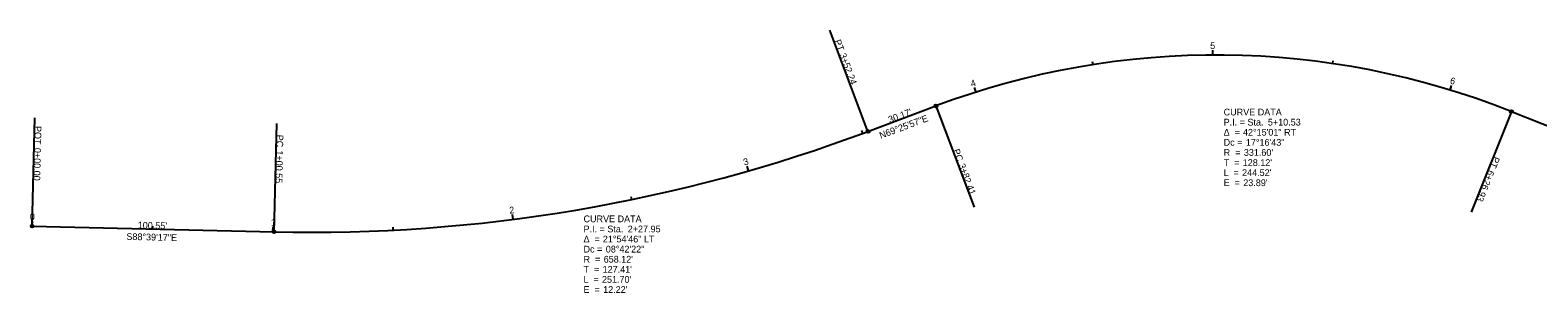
# Model space of a CAD drawing. Extents: x 2001143 to 2002244, y 252727 to 252963.
# Drawn here: x 2001143 to 2001769, y 252823 to 252933 of the extents above; entities that cross this region are included whole.
import ezdxf

# ---------------------------------------------------------------- set-up
doc = ezdxf.new("R2010")
doc.units = 0
for name, color, linetype in [('DT_P_Break_Line', 7, 'Continuous'), ('DT_P_Contour_Major', 7, 'Continuous'), ('DT_P_Contour_Minor', 7, 'Continuous'), ('DT_P_Spot_Elevations', 7, 'Continuous'), ('DT_P_Void', 7, 'Continuous'), ('DT_X_Contour_Minor', 7, 'Continuous'), ('DT_X_Spot_Elev', 7, 'Continuous')]:
    doc.layers.add(name, color=color, linetype=linetype)

msp = doc.modelspace()

# ---------------------------------------------------------------- linework, layer by layer
at = {"layer": 'DT_P_Break_Line'}
for p, q in [((2001490.69, 252890.46), (2001474.88, 252932.6)), ((2001633.98, 252922.2), (2001633.98, 252924.2)), ((2001535.56, 252906.8), (2001535.2, 252907.95)), ((2001732.54, 252907.66), (2001732.89, 252908.81)), ((2001518.94, 252901.06), (2001534.75, 252858.93)), ((2001757.95, 252898.74), (2001741.32, 252856.92)), ((2001143.52, 252851.06), (2001144.57, 252896.05)), ((2001244.04, 252848.7), (2001245.09, 252893.68)), ((2001441.1, 252874.07), (2001440.77, 252875.22)), ((2001343.26, 252853.87), (2001343.11, 252855.06)), ((2001143.52, 252851.06), (2001143.56, 252853.06)), ((2001243.49, 252848.71), (2001243.52, 252849.91))]:
    msp.add_line(p, q, dxfattribs=at)
for centre in [(2001518.94, 252901.06), (2001757.95, 252898.74), (2001490.69, 252890.46), (2001143.52, 252851.06), (2001244.04, 252848.7)]:
    msp.add_circle(centre, 0.6, dxfattribs=at)
at = {"layer": 'DT_P_Contour_Minor'}
for p, q in [((2001490.69, 252890.46), (2001518.94, 252901.06)), ((2001757.95, 252898.74), (2001890.21, 252846.15)), ((2001143.52, 252851.06), (2001244.04, 252848.7))]:
    msp.add_line(p, q, dxfattribs=at)
for centre, radius, start, end in [((2001635.43, 252590.6), 331.6, 68.31729, 110.5675), ((2001635.43, 252590.6), 331.6, 68.31729, 110.5675), ((2001259.49, 253506.63), 658.12, 268.65462, 290.5675), ((2001259.49, 253506.63), 658.12, 268.65462, 290.5675)]:
    msp.add_arc(centre, radius, start, end, dxfattribs=at)
at = {"layer": 'DT_P_Spot_Elevations'}
for p, q in [((2001490.69, 252890.46), (2001474.88, 252932.6)), ((2001633.98, 252922.2), (2001633.98, 252924.2)), ((2001584.19, 252918.22), (2001584.01, 252919.4)), ((2001683.81, 252918.65), (2001683.99, 252919.84)), ((2001535.56, 252906.8), (2001534.96, 252908.71)), ((2001732.54, 252907.66), (2001733.13, 252909.57)), ((2001518.94, 252901.06), (2001534.75, 252858.93)), ((2001757.95, 252898.74), (2001741.32, 252856.92)), ((2001143.52, 252851.06), (2001144.57, 252896.05)), ((2001244.04, 252848.7), (2001245.09, 252893.68)), ((2001488.59, 252889.68), (2001488.17, 252890.8)), ((2001441.1, 252874.07), (2001440.55, 252875.99)), ((2001392.56, 252862.11), (2001392.32, 252863.29)), ((2001343.26, 252853.87), (2001343.01, 252855.85)), ((2001143.52, 252851.06), (2001143.56, 252853.06)), ((2001193.5, 252849.88), (2001193.53, 252851.08)), ((2001243.49, 252848.71), (2001243.54, 252850.71)), ((2001293.47, 252849.39), (2001293.41, 252850.59))]:
    msp.add_line(p, q, dxfattribs=at)
for centre in [(2001518.94, 252901.06), (2001757.95, 252898.74), (2001490.69, 252890.46), (2001143.52, 252851.06), (2001244.04, 252848.7)]:
    msp.add_circle(centre, 0.6, dxfattribs=at)
at = {"layer": 'DT_X_Contour_Minor'}
for p, q in [((2001490.69, 252890.46), (2001474.88, 252932.6)), ((2001633.98, 252922.2), (2001633.98, 252923.4)), ((2001518.94, 252901.06), (2001534.75, 252858.93)), ((2001757.95, 252898.74), (2001741.32, 252856.92)), ((2001143.52, 252851.06), (2001144.57, 252896.05)), ((2001244.04, 252848.7), (2001245.09, 252893.68)), ((2001143.52, 252851.06), (2001143.56, 252853.06))]:
    msp.add_line(p, q, dxfattribs=at)
for centre in [(2001518.94, 252901.06), (2001757.95, 252898.74), (2001490.69, 252890.46), (2001143.52, 252851.06), (2001244.04, 252848.7)]:
    msp.add_circle(centre, 0.6, dxfattribs=at)

# ---------------------------------------------------------------- texts
at = {"layer": 'DT_P_Break_Line'}
for s, rotation, p in [('PT', 290.5675, (2001476.63, 252928.06)), ('5', 0.24994, (2001632.85, 252924.74)), ('3+52.24', 290.5675, (2001478.77, 252922.37)), ('POT', 268.65462, (2001144.54, 252892.75)), ('PC', 268.65462, (2001245.03, 252889.1)), ('0+00.00', 268.65462, (2001144.33, 252883.62)), ('1+00.55', 268.65462, (2001244.88, 252882.58)), ('PC', 290.5675, (2001525.93, 252882.57)), ('PT', 248.31729, (2001750.66, 252880.29)), ('3+82.41', 290.5675, (2001528.22, 252876.47)), ('6+26.93', 248.31729, (2001748.41, 252874.63)), ('0', 358.65462, (2001142.47, 252853.63))]:
    msp.add_text(s, height=2.8, rotation=rotation, dxfattribs=at).set_placement(p)
at = {"layer": 'DT_P_Contour_Major'}
for s, rotation, p in [("30.17'", 20.5675, (2001499.74, 252893.91)), ('N69°25\'57"E', 20.5675, (2001496.03, 252887.34)), ('S88°39\'17"E', 358.65462, (2001182.59, 252845.34)), ("100.55'", 358.65462, (2001187.29, 252850.08))]:
    msp.add_text(s, height=2.8, rotation=rotation, dxfattribs=at).set_placement(p)
for s, p in [('CURVE DATA', (2001638.44, 252897.1)), ('P.I. = Sta. ', (2001638.44, 252892.9)), ('5+10.53', (2001656.81, 252892.9)), ('Δ  = ', (2001638.44, 252888.7)), ('Dc = ', (2001638.44, 252884.5)), ('42°15\'01" RT', (2001646.46, 252888.7)), ('17°16\'43"', (2001647.68, 252884.5)), ('R  = ', (2001638.44, 252880.3)), ("331.60'", (2001646.81, 252880.3)), ('T  = ', (2001638.44, 252876.1)), ('L  = ', (2001638.44, 252871.9)), ("244.52'", (2001646.09, 252871.9)), ("128.12'", (2001646.37, 252876.1)), ('E  = ', (2001638.44, 252867.7)), ("23.89'", (2001646.59, 252867.7)), ('CURVE DATA', (2001372.52, 252852.68)), ('P.I. = Sta. ', (2001372.52, 252848.48)), ('2+27.95', (2001390.89, 252848.48)), ('Δ  = ', (2001372.52, 252844.28)), ('Dc = ', (2001372.52, 252840.08)), ('21°54\'46" LT', (2001380.54, 252844.28)), ('08°42\'22"', (2001381.76, 252840.08)), ('R  = ', (2001372.52, 252835.88)), ("658.12'", (2001380.89, 252835.88)), ('T  = ', (2001372.52, 252831.68)), ('L  = ', (2001372.52, 252827.48)), ("251.70'", (2001380.17, 252827.48)), ("127.41'", (2001380.45, 252831.68)), ('E  = ', (2001372.52, 252823.28)), ("12.22'", (2001380.67, 252823.28))]:
    msp.add_text(s, height=2.8, dxfattribs=at).set_placement(p)
at = {"layer": 'DT_P_Spot_Elevations'}
for s, rotation, p in [('PT', 290.5675, (2001476.63, 252928.06)), ('5', 0.24994, (2001632.85, 252924.74)), ('3+52.24', 290.5675, (2001478.77, 252922.37)), ('4', 17.52864, (2001533.79, 252908.87)), ('6', 342.97124, (2001732.22, 252910.42)), ('POT', 268.65462, (2001144.54, 252892.75)), ('PC', 268.65462, (2001245.03, 252889.1)), ('0+00.00', 268.65462, (2001144.33, 252883.62)), ('1+00.55', 268.65462, (2001244.88, 252882.58)), ('PC', 290.5675, (2001525.93, 252882.57)), ('PT', 248.31729, (2001750.66, 252880.29)), ('3', 16.01907, (2001439.35, 252876.22)), ('3+82.41', 290.5675, (2001528.22, 252876.47)), ('6+26.93', 248.31729, (2001748.41, 252874.63)), ('0', 358.65462, (2001142.47, 252853.63)), ('2', 7.31304, (2001341.85, 252856.21)), ('1', 358.65462, (2001242.61, 252851.23))]:
    msp.add_text(s, height=2.8, rotation=rotation, dxfattribs=at).set_placement(p)
at = {"layer": 'DT_P_Void'}
for s, rotation, p in [("30.17'", 20.5675, (2001499.74, 252893.91)), ('N69°25\'57"E', 20.5675, (2001496.03, 252887.34)), ('S88°39\'17"E', 358.65462, (2001182.59, 252845.34)), ("100.55'", 358.65462, (2001187.29, 252850.08))]:
    msp.add_text(s, height=2.8, rotation=rotation, dxfattribs=at).set_placement(p)
for s, p in [('CURVE DATA', (2001638.44, 252897.1)), ('P.I. = Sta. ', (2001638.44, 252892.9)), ('5+10.53', (2001656.81, 252892.9)), ('Δ  = ', (2001638.44, 252888.7)), ('Dc = ', (2001638.44, 252884.5)), ('42°15\'01" RT', (2001646.46, 252888.7)), ('17°16\'43"', (2001647.68, 252884.5)), ('R  = ', (2001638.44, 252880.3)), ("331.60'", (2001646.81, 252880.3)), ('T  = ', (2001638.44, 252876.1)), ('L  = ', (2001638.44, 252871.9)), ("244.52'", (2001646.09, 252871.9)), ("128.12'", (2001646.37, 252876.1)), ('E  = ', (2001638.44, 252867.7)), ("23.89'", (2001646.59, 252867.7)), ('CURVE DATA', (2001372.52, 252852.68)), ('P.I. = Sta. ', (2001372.52, 252848.48)), ('2+27.95', (2001390.89, 252848.48)), ('Δ  = ', (2001372.52, 252844.28)), ('Dc = ', (2001372.52, 252840.08)), ('21°54\'46" LT', (2001380.54, 252844.28)), ('08°42\'22"', (2001381.76, 252840.08)), ('R  = ', (2001372.52, 252835.88)), ("658.12'", (2001380.89, 252835.88)), ('T  = ', (2001372.52, 252831.68)), ('L  = ', (2001372.52, 252827.48)), ("251.70'", (2001380.17, 252827.48)), ("127.41'", (2001380.45, 252831.68)), ('E  = ', (2001372.52, 252823.28)), ("12.22'", (2001380.67, 252823.28))]:
    msp.add_text(s, height=2.8, dxfattribs=at).set_placement(p)
at = {"layer": 'DT_X_Contour_Minor'}
for s, rotation, p in [('PT', 290.5675, (2001476.63, 252928.06)), ('3+52.24', 290.5675, (2001478.77, 252922.37)), ('POT', 268.65462, (2001144.54, 252892.75)), ('PC', 268.65462, (2001245.03, 252889.1)), ('0+00.00', 268.65462, (2001144.33, 252883.62)), ('1+00.55', 268.65462, (2001244.88, 252882.58)), ('PC', 290.5675, (2001525.93, 252882.57)), ('PT', 248.31729, (2001750.66, 252880.29)), ('3+82.41', 290.5675, (2001528.22, 252876.47)), ('6+26.93', 248.31729, (2001748.41, 252874.63)), ('0', 358.65462, (2001142.47, 252853.63))]:
    msp.add_text(s, height=2.8, rotation=rotation, dxfattribs=at).set_placement(p)
at = {"layer": 'DT_X_Spot_Elev'}
for s, rotation, p in [("30.17'", 20.5675, (2001499.74, 252893.91)), ('N69°25\'57"E', 20.5675, (2001496.03, 252887.34)), ('S88°39\'17"E', 358.65462, (2001182.59, 252845.34)), ("100.55'", 358.65462, (2001187.29, 252850.08))]:
    msp.add_text(s, height=2.8, rotation=rotation, dxfattribs=at).set_placement(p)
for s, p in [('CURVE DATA', (2001638.44, 252897.1)), ('P.I. = Sta. ', (2001638.44, 252892.9)), ('5+10.53', (2001656.81, 252892.9)), ('Δ  = ', (2001638.44, 252888.7)), ('Dc = ', (2001638.44, 252884.5)), ('42°15\'01" RT', (2001646.46, 252888.7)), ('17°16\'43"', (2001647.68, 252884.5)), ('R  = ', (2001638.44, 252880.3)), ("331.60'", (2001646.81, 252880.3)), ('T  = ', (2001638.44, 252876.1)), ('L  = ', (2001638.44, 252871.9)), ("244.52'", (2001646.09, 252871.9)), ("128.12'", (2001646.37, 252876.1)), ('E  = ', (2001638.44, 252867.7)), ("23.89'", (2001646.59, 252867.7)), ('CURVE DATA', (2001372.52, 252852.68)), ('P.I. = Sta. ', (2001372.52, 252848.48)), ('2+27.95', (2001390.89, 252848.48)), ('Δ  = ', (2001372.52, 252844.28)), ('Dc = ', (2001372.52, 252840.08)), ('21°54\'46" LT', (2001380.54, 252844.28)), ('08°42\'22"', (2001381.76, 252840.08)), ('R  = ', (2001372.52, 252835.88)), ("658.12'", (2001380.89, 252835.88)), ('T  = ', (2001372.52, 252831.68)), ('L  = ', (2001372.52, 252827.48)), ("251.70'", (2001380.17, 252827.48)), ("127.41'", (2001380.45, 252831.68)), ('E  = ', (2001372.52, 252823.28)), ("12.22'", (2001380.67, 252823.28))]:
    msp.add_text(s, height=2.8, dxfattribs=at).set_placement(p)

doc.saveas('drawing.dxf')
